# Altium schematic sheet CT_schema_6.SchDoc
size 224 x 258 mm
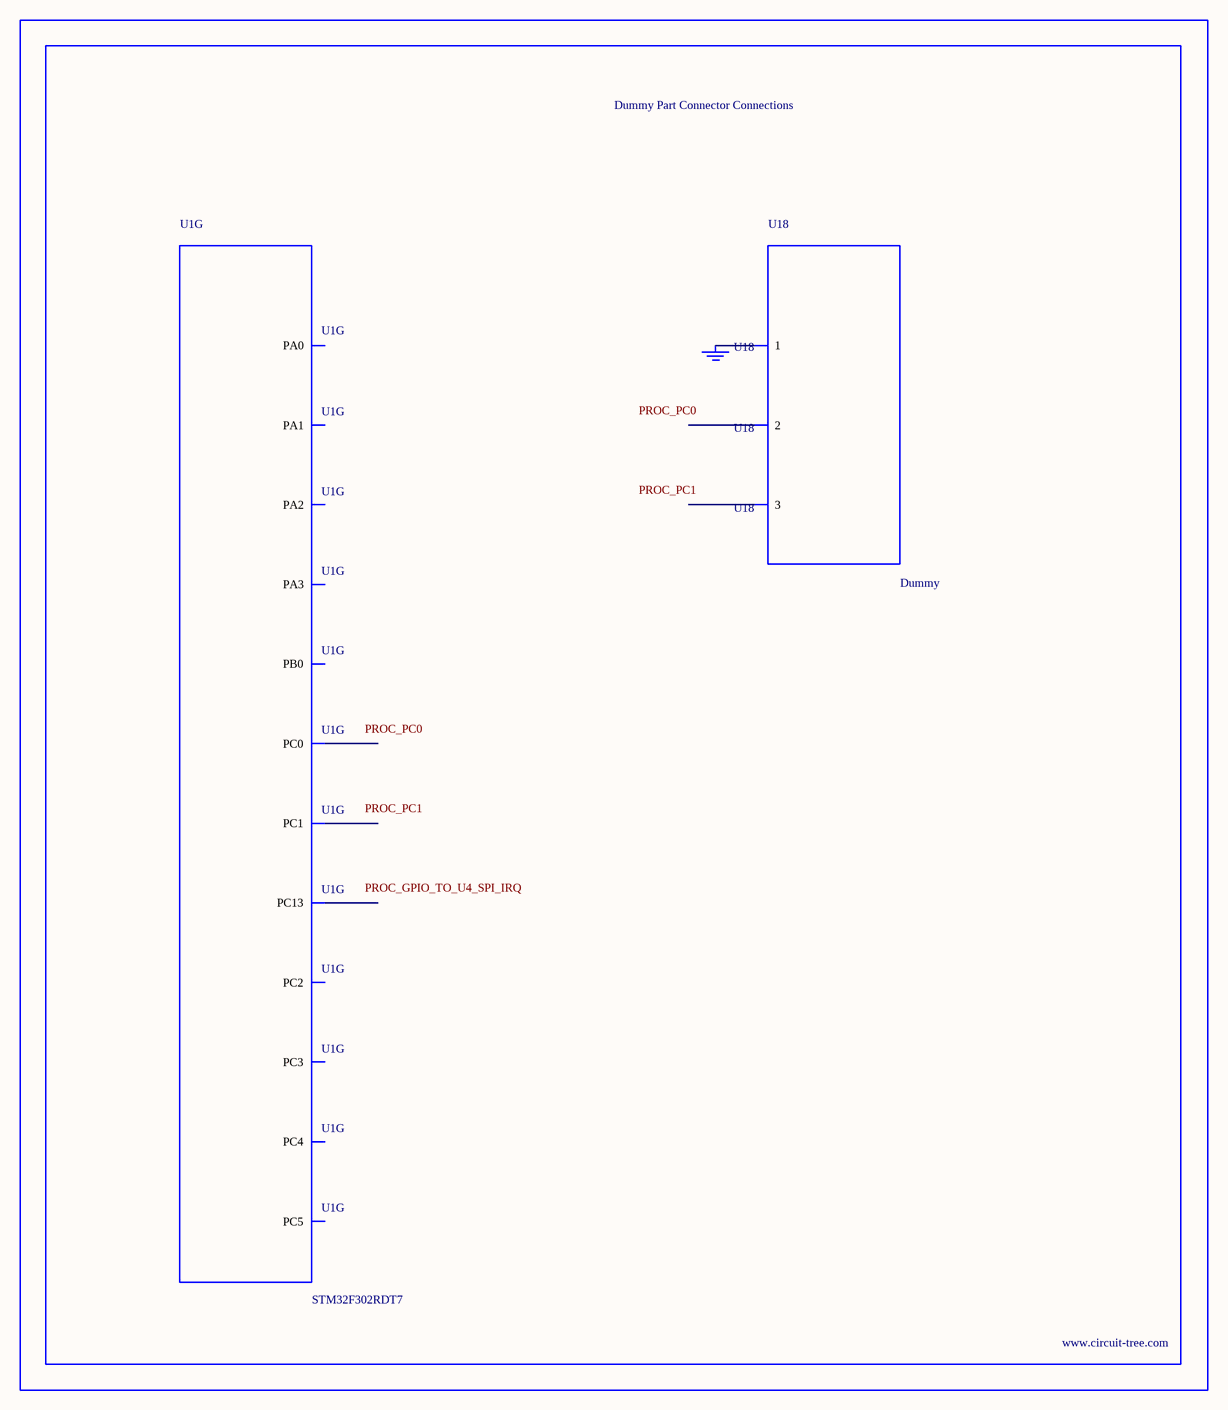
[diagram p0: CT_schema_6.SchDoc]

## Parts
BORDER5  (no value)
GND_INSTANCE_5_0  (no value)
U1  STM32F302RDT7  [LQFP64]  (part G of 7)
U18  Dummy  [DUMMY_PACKAGE_180]

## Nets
NetGND_INSTANCE_5_0_0: GND_INSTANCE_5_0.0(GND) U18.1

Not connected (* = marked no-connect by the designer): U1 2(PC13) 8(PC0) 9(PC1) 10(PC2) 11(PC3) 14(PA0) 15(PA1) 16(PA2) 17(PA3) 24(PC4) 25(PC5) 26(PB0); U18 2 3

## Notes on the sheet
- Labels drawn without touching a wire or pin: PROC_GPIO_TO_U4_SPI_IRQ, PROC_PC0, PROC_PC1

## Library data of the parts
BORDER5 = BORDER_PAGE5
GND_INSTANCE_5_0 = GND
